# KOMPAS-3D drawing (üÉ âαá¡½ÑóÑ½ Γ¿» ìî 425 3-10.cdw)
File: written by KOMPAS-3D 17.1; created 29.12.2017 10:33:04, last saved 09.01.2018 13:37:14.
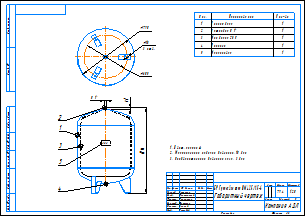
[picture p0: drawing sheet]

Sheet 1: A3, landscape, title-block layout from C:\Лощинин\GRAPHIC.LYT style 1

Title block, sheet 1: name: БР Гранлевел тип НМ 425/1,5-6 / Габаритный чертеж; mass: 79,4; sheets: 1; sheet format: A3; stored path: \\Fsk1\files\АП\20_PKO\02_Насосное направление\Разработка\04_Проекты разные\Баки\КД действующая\Баки Flexcon R\Компас\Чертежи\БР Гранлевел тип НМ 425 1,5-6.cdw; drawn by: Лощинин; checked by: Хантимеров

Views: Проекционный вид 2
Referenced files in \\Fsk1\files\АП\20_PKO\02_Насосное направление\Разработка\04_Проекты разные\Баки\КД действующая\Баки Flexcon R\Компас\: 425 литров.a3d, 16422_Flexcon_425_1-6.m3d
Referenced files in C:\Лощинин\: GRAPHIC.LYT
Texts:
  IvAn
  ADL
  Поз.
  Кол-во
  Корпус бака
  Мембрана SBR
  Патрубок G 1"
  Ниппель
  Маркировка
  АДЛ
  Цвет: красный
  Максимальное рабочее давление: 10 бар
  Предварительное давление газа: 3 бар
  ACAD_ISO03W100_RGB_223_127_255_SC_0.063_THICK_0.05
  ACAD_ISO03W100_RGB_223_127_255_SC_1_THICK_0.05
  Лит-Масса-Масштаб
  Материал-Предприятие
  Масштаб
  Изм.
  Лист
  № докум.
  Подп.
  Дата
  Лит.
  Разраб.
  Пров.
  Т.контр.
  Курлыкина
  Листов
  Нач.отд.
  Щетинин
  Н.контр.
  Долгов
  Утв.
  Рашидов
  Компания АДЛ
  Изменение
  Номер документа
  Подпись
  Обозначение документа
  Наименование изделия
  Масса изделия по ГОСТ 2.109-73
  Порядковый номер листа
  Общее количество листов в документе
  Характер работы, выполненной лицом, подписавшим документ
  Наименование или индекс предприятия, выпускающего документ
  Инв. № подл.
  Подп. и дата
  Взам. инв. №
  Инв. № дубл.
  Инвентарный номер подлинника по ГОСТ 2.501-68
  Подпись принявшего подлинник в отдел технической документации
  Инвентарный номер подлинника, взамен которого выпущен данный подлинник
  Инвентарный номер дубликата по ГОСТ 2.502-68
  Подпись принявшего дубликат в отдел технической документации
  Справ. №
  Перв. примен.
  Обозначение документа, взамен или на основании которого выпущен данный документ
  Обозначение документа, в котором впервые записан данный документ
  Подпись лица, копировавшего чертеж
  Обозначение формата листа
Dimensions and other numbers on the sheet: 1; 3; 2; 4; 5; 21; 1:20; 79,4; 16422_Flexcon_425_1-6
